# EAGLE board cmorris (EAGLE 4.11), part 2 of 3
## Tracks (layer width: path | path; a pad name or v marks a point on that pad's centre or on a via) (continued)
DQ6  (via drill 0.61)
  Top 0.203: v56.53,59.14 56.94,58.74 56.94,45.4 56.53,45 56.53,44.29 56.94,43.88 56.94,30.7 v56.53,30.29 | v78.86,25.64 v78.86,30.29 | v82.24,26.63 82.19,26.58 82.19,25.64 IC9.6
  Bottom 0.203: v56.53,59.14 39.75,59.14 39.39,59.5 IC17.13 | v78.86,30.29 v56.53,30.29 | v78.86,25.64 79.6,25.64 IC9.6 | v82.24,26.63 100.71,26.63 101.06,26.99 IC6.5
DQ7  (via drill 0.61)
  Top 0.203: v89.89,21.53 90.29,21.93 90.29,31.33 v89.89,31.74 90.29,32.04 90.29,39.74 v89.48,40.55 | v27.71,62.5 28.11,62.09 28.11,55.11 27.3,54.29 v27.3,48.43 | v34.41,44.21 v34.41,48.43 | v41.27,41.92 v41.27,43.9 | v76.22,40.68 v76.22,41.49
  Bottom 0.203: v89.89,31.74 90.47,31.74 90.78,32.04 101.04,32.04 101.06,32.07 IC6.3 | v89.89,21.53 89.66,21.3 82.16,21.3 81.81,20.94 IC9.8 | v27.71,62.5 37.18,62.5 IC17.12 | v34.41,48.43 v27.3,48.43 | v34.41,44.21 34.72,43.9 v41.27,43.9 | v41.27,41.92 41.45,41.75 51.66,41.75 51.73,41.82 52.24,41.82 52.7,41.36 55.49,41.36 55.6,41.47 56.08,41.47 56.38,41.77 75.94,41.77 v76.22,41.49 | v76.22,40.68 76.35,40.55 v89.48,40.55
DQ8  (via drill 0.61)
  Top 0.203: v113.74,33.44 113.71,33.41 113.71,31.56 113.74,31.53 v113.74,24.42 | v99.69,27.45 v99.69,24.07 | v98.47,27.45 98.06,27.04 v98.06,15.15 | v35.63,67.58 35.63,34.38 35.22,33.97 35.22,33.26 35.63,32.86 v35.63,12.84 | v72.89,23.53 v72.89,15.05
  Bottom 0.203: v113.74,33.44 115.08,33.44 115.39,33.74 130.42,33.74 130.78,33.39 IC2.18 | v113.74,24.42 110.94,24.42 110.59,24.07 v99.69,24.07 99.21,23.84 78.84,23.84 78.51,23.51 77.72,23.51 77.69,23.53 v72.89,23.53 | v98.47,27.45 v99.69,27.45 | v98.06,15.15 98.01,15.2 IC9.11 | v35.63,67.58 37.18,67.58 IC17.10 | v35.63,12.84 58.87,12.84 59.18,12.54 60.45,12.54 60.47,12.56 61.13,12.56 61.16,12.54 62.99,12.54 63.88,13.42 65.48,13.42 67.1,15.05 v72.89,15.05
DQ9  (via drill 0.61)
  Top 0.203: v98.88,25.82 98.47,25.41 98.47,19.88 v98.88,19.47 | v37.66,28.79 37.66,36.67 36.85,37.48 36.85,66.46 39.19,66.46 40.1,67.37 40.1,69.71 39.77,70.04 IC17.9 | v47.44,24.65 47.85,24.24 47.85,15.07 v47.44,14.67 | v54.5,17.46 v54.5,14.67
  Bottom 0.203: v98.88,25.82 100.48,25.82 101.29,26.63 125.06,26.63 125.09,26.66 130.45,26.66 130.78,26.99 IC2.16 | v98.88,19.47 98.85,19.5 89.56,19.5 89.43,19.62 IC9.13 87.6,19.62 86.33,18.35 82.32,18.35 81.91,18.76 79.88,18.76 78.73,17.61 59.1,17.61 58.95,17.46 v54.5,17.46 | v37.66,28.79 39.62,28.79 40.76,27.65 40.76,25.49 41.78,25.49 42.62,24.65 v47.44,24.65 | v54.5,14.67 v47.44,14.67
DQ10  (via drill 0.61)
  Top 0.203: v50.87,73.11 50.87,71.84 51.28,71.44 51.28,58.74 v50.87,58.33 | v63.34,58.26 63.34,48.58 63.75,48.17 v63.75,27.27 | v78.05,24.35 v78.05,27.27 | v96.79,25.08 v96.79,21.55
  Bottom 0.203: v50.87,73.11 39.77,73.11 IC17.8 | v50.87,58.33 51.18,58.64 55.88,58.64 56.26,58.26 v63.34,58.26 | v78.05,27.27 v63.75,27.27 | v78.05,24.35 87.24,24.35 87.6,24.7 IC9.15 89.81,25.08 v96.79,25.08 | v96.79,21.55 130.42,21.55 130.78,21.91 IC2.14
DQ11  (via drill 0.61)
  Top 0.203: v77.87,32.86 v77.87,31.94 | v53,36.31 v53,33.16 | v36.85,36.31 36.44,36.72 36.44,66.64 36.85,67.04 36.85,74.79 37.18,75.12 IC17.7 | v130.07,31.48 130.07,18.1 130.4,17.77 IC2.12
  Bottom 0.203: v77.87,31.94 81.61,31.94 82.39,31.15 87.55,31.15 87.6,31.1 IC9.17 89.63,30.9 90.22,30.9 90.93,31.61 113.66,31.61 113.81,31.46 114.47,31.46 114.73,31.71 122.98,31.71 123.01,31.69 126.06,31.69 126.18,31.56 129.99,31.56 v130.07,31.48 | v77.87,32.86 65.6,32.86 65.27,33.19 61.54,33.19 61.21,32.86 53.31,32.86 v53,33.16 | v36.85,36.31 v53,36.31
DRL  (via drill 0.61)
  Top 0.203: v148.79,57.6 149.37,58.18 149.37,63.36 149.7,63.69 IC5.2
  Bottom 0.203: v148.79,57.6 136.04,57.6 135.68,57.24 IC7.5
DRL\
  Top 0.203: IC7.6 133.45,53.79 133.12,53.45 133.12,50.2 133.45,49.87 133.45,41.26 133.42,41.24 133.42,25.82 132.99,25.39 IC2.15
EA1  (via drill 0.61)
  Top 0.203: v145.79,16.17 145.79,17.69 IC16.3 | v136.34,26.12 v136.34,16.47 | v127.73,24.42 v127.73,25.84 | v115.03,24.37 115.03,18.4 114.19,17.56 114.19,16.85 v113.79,16.45 | v93.82,16.78 93.54,16.5 v93.54,14.36 | v91.36,2.99 91.36,4.1 90.7,4.76 90.7,13.96 v90.29,14.36 90.7,14.67 v90.7,40.7 | SV1.5 v104.14,3.11 | v63.98,85.28 63.57,84.87 63.57,83.55 63.01,83 63.01,81.98 v62.91,81.88 | v45.99,81.55 46.4,81.14 46.4,74.92 45.99,74.51 45.99,71.41 v45.59,71.01 | v34.01,71.03 34.01,66.87 34.41,66.46 34.41,55.13 33.6,54.32 v33.6,50.56 | v34.82,50.56 35.22,50.15 35.22,39.59 v34.82,39.18 | v37.66,39.18 37.66,37.25 38.07,36.84 38.07,30.11 v38.58,29.6 | v49.14,29.48 49.14,28.46 IC19.2 | v81.71,41.47 81.71,54.7 81.3,55.11 81.3,77.41 80.92,77.79 v80.92,89.93 | v69.57,89.85 69.57,86.55 69.23,86.22 IC10.11
  Bottom 0.203: v145.79,16.17 145.46,16.5 138.25,16.5 138.22,16.47 v136.34,16.47 | v136.34,26.12 128.01,26.12 v127.73,25.84 | v127.73,24.42 127.25,24.42 126.44,23.61 125.78,23.61 125.37,24.02 122.4,24.02 122.37,24.04 121.71,24.04 121.66,23.99 115.41,23.99 v115.03,24.37 | v113.79,16.45 94.15,16.45 v93.82,16.78 | v90.29,14.36 v93.54,14.36 | v91.36,2.99 99.72,2.99 99.84,3.11 v104.14,3.11 | v63.98,85.28 66.98,85.28 67,85.31 IC10.11 | v62.91,81.88 62.88,81.9 56.38,81.9 55.98,81.5 55.32,81.5 54.91,81.9 46.35,81.9 v45.99,81.55 | v45.59,71.01 39.82,71.01 39.49,71.34 34.31,71.34 v34.01,71.03 | v34.82,50.56 v33.6,50.56 | v37.66,39.18 v34.82,39.18 | v38.58,29.6 38.7,29.48 v49.14,29.48 | v90.7,40.7 89.94,41.47 v81.71,41.47 | v80.92,89.93 80.51,90.34 76.53,90.34 76.04,89.85 v69.57,89.85
EA2  (via drill 0.61)
  Top 0.203: v60.9,3.42 v60.9,1.94 | v50.64,10.2 v50.64,3.42 | v45.03,10.2 45.44,10.61 45.44,24.73 44.95,25.21 44.95,26.2 IC19.4 | v106.68,1.94 SV1.7 | v144.5,15.66 144.5,17.67 IC16.2 | v134.56,16.45 134.16,16.04 134.16,15.81 133.32,14.97 133.32,3.19 131.26,1.13 124.48,1.13 v124.48,1.94
  Bottom 0.203: 105.93,1.19 105.86,1.13 61.72,1.13 v60.9,1.94 | 105.93,1.19 v106.68,1.94 | v50.64,3.42 v60.9,3.42 | v45.03,10.2 v50.64,10.2 | v144.5,15.66 135.53,15.66 134.74,16.45 v134.56,16.45 | v124.48,1.94 123.67,1.13 105.99,1.13 105.93,1.19
EA3  (via drill 0.61)
  Top 0.203: v39.95,9.05 40.36,9.46 40.36,25.72 39.87,26.2 IC19.6 | v37.26,1.94 v37.26,9.05 | v59.68,1.94 60.09,2.35 60.09,3.82 60.52,4.25 61.49,4.25 61.49,4 62.12,3.37 v62.12,3.01 | v74.75,3.01 75.48,2.27 78.68,2.27 v78.68,3.01 | v86.97,2.15 v86.97,3.01 | v97.94,6.16 v97.94,2.15 | v153.41,9.72 153.41,17.69 IC16.6 | v145.18,11.11 v145.18,9.72 | v131.64,12.71 v131.64,11.09 | v126.92,12.71 126.51,13.12 126.51,18.61 v126.92,19.01 | v113.74,19.75 113.38,19.39 v113.38,17.67 | v115.41,3.92 v115.41,17.03
  Bottom 0.203: v37.26,9.05 v39.95,9.05 | v37.26,1.94 38.07,1.13 58.87,1.13 v59.68,1.94 | v74.75,3.01 v62.12,3.01 | v86.97,3.01 v78.68,3.01 | v97.94,2.15 v86.97,2.15 | v97.94,6.16 108.56,6.16 108.91,5.8 SV1.9 109.52,4.28 109.88,3.92 v115.41,3.92 | v145.18,9.72 v153.41,9.72 | v145.18,11.11 142.44,11.11 142.29,10.96 131.77,10.96 v131.64,11.09 | v131.64,12.71 131.54,12.61 127.02,12.61 v126.92,12.71 | v126.92,19.01 121.48,19.01 121.31,19.19 120.72,19.19 120.52,19.39 114.09,19.39 v113.74,19.75 | v113.38,17.67 113.76,17.29 115.16,17.29 v115.41,17.03
EA\  (via drill 0.61)
  Top 0.203: v95.78,3.85 v95.78,12 | v83.46,2.17 v83.46,3.85 | v68.73,2.17 68.73,7.99 70.05,9.31 70.05,14.74 70.45,15.15 70.45,20 70.86,20.41 70.86,33.24 70.45,33.64 70.45,34.35 71.67,35.57 71.67,49.26 71.32,49.62 71.32,51.5 70.51,52.31 70.51,56.25 70.1,56.66 70.1,58.59 69.44,59.25 69.44,62.22 68.32,63.34 65.78,63.34 65.78,64.99 64.97,65.8 64.97,75.96 65.09,76.09 65.09,82.49 v65.5,82.89 | v101.59,12 SV1.4
  Bottom 0.203: v95.78,12 v101.59,12 | v83.46,3.85 v95.78,3.85 | v68.73,2.17 v83.46,2.17 | v65.5,82.89 66.87,82.89 IC10.10
EMA1  (via drill 0.61)
  Top 0.203: v8.63,25.49 8.63,23.51 IC14.3 | v52.19,73.95 52.19,74.89 52.42,75.12 IC17.34 | v30.96,73.9 30.55,73.5 30.55,25.59 v30.96,25.18
  Bottom 0.203: 30.96,25.49 33.57,25.49 33.9,25.82 IC19.8 | 30.96,25.49 v8.63,25.49 | v52.19,73.95 47.19,73.95 47.14,73.9 v30.96,73.9 | 30.96,25.49 v30.96,25.18
EMA2  (via drill 0.61)
  Top 0.203: v6.09,20.46 6.09,21.63 IC14.2 | v44.93,78.07 44.93,76.06 44.52,75.65 44.52,43.35 44.11,42.94 44.11,32.37 v44.52,31.97 | v28.01,31.97 28.01,20.89 28.44,20.46 IC19.11
  Bottom 0.203: v6.09,20.46 28.44,20.46 IC19.11 | v44.93,78.07 52.42,78.07 IC17.35 | v28.01,31.97 v44.52,31.97
EMA3  (via drill 0.61)
  Top 0.203: v4.36,28.16 4.36,32.58 3.96,32.98 3.96,47.89 3.55,48.3 IC4.1 | v15.41,28.16 15.01,27.75 15.01,23.53 IC14.6 | v48.43,80.2 48.03,79.79 48.03,74.21 47.62,73.8 47.62,63.67 48.43,62.85 v48.43,58.33 | v45.59,58.33 45.99,57.93 45.99,53.76 46.4,53.35 46.4,45.5 v45.99,45.1 | v42.49,45.1 42.49,43.52 42.9,43.12 42.9,23.2 v42.49,22.8 | v34.41,22.8 34.41,20.84 IC19.13
  Bottom 0.203: IC14.6 15.87,21.25 16.2,20.92 28.44,20.92 28.7,21.17 33.57,21.17 33.9,20.84 IC19.13 | v15.41,28.16 v4.36,28.16 | v48.43,80.2 52.42,80.2 IC17.36 | v45.59,58.33 v48.43,58.33 | v42.49,45.1 v45.99,45.1 | v34.41,22.8 v42.49,22.8
EMA4  (via drill 0.61)
  Top 0.203: v38.98,24.22 38.98,20.84 IC19.15 | v11.7,47.59 11.7,28.94 11.98,28.66 v11.98,24.32 | v40.43,71.84 v40.43,82.36 | v29.33,71.84 29.74,71.44 29.74,47.99 v29.33,47.59
  Bottom 0.203: 18.74,24.22 18.41,23.89 IC14.7 | v38.98,24.22 18.74,24.22 | v11.98,24.32 18.71,24.32 18.74,24.22 | IC4.2 5.71,47.92 6.04,47.59 v11.7,47.59 v29.33,47.59 | v40.43,82.36 52.8,82.36 IC17.37 | v29.33,71.84 v40.43,71.84
EMA5  (via drill 0.61)
  Top 0.203: v8.38,14.49 8.38,11.06 IC15.3 | v44.06,14.49 44.06,18.2 IC19.17 43.68,20.46 43.3,20.84 v43.3,43.88 | v6.17,24.47 6.57,24.88 6.57,29.04 6.62,29.1 6.62,36.51 6.98,36.87 6.98,47.92 7.36,48.3 IC4.3 | v4.19,14.49 v4.19,24.47 | v47.62,84.9 47.62,74.38 47.21,73.98 47.21,62.9 v47.62,62.5 | v45.59,62.5 45.99,62.09 45.99,59.25 46.4,58.84 46.4,53.94 46.81,53.53 46.81,44.29 v46.4,43.88
  Bottom 0.203: v44.06,14.49 v8.38,14.49 v4.19,14.49 | v4.19,24.47 v6.17,24.47 | v47.62,84.9 52.8,84.9 IC17.38 | v45.59,62.5 v47.62,62.5 | v43.3,43.88 v46.4,43.88
EWL  (via drill 0.61)
  Top 0.203: v90.6,98.54 90.6,96.69 89.68,95.77 89.68,92.42 89.02,92.42 88.03,91.43 88.03,89.6 88.44,89.19 88.44,88.84 IC20.2 | v97.71,99.45 v97.71,98.41 | v111.04,99.45 111.04,95.64 110.31,94.91 110.31,86.02 111.12,85.2 111.12,81.17 111.53,80.76 111.53,78.8 111.86,78.47 IC18.9 | v137.26,67.35 136.85,67.76 136.85,75.86 v137.26,76.26 | v133.5,76.26 133.5,84.92 v133.9,85.33 | v115.62,78.47 v115.62,85.36
  Bottom 0.203: v90.6,98.54 93.62,98.54 94.03,98.13 94.48,98.13 94.94,97.68 95.7,97.68 95.73,97.7 97,97.7 v97.71,98.41 | v97.71,99.45 97.73,99.48 111.02,99.48 v111.04,99.45 | v137.26,67.35 137.64,67.73 142.69,67.73 142.72,67.76 143.4,67.76 144.06,67.09 150.01,67.09 IC5.1 | v133.5,76.26 v137.26,76.26 | v133.9,85.33 133.78,85.2 115.77,85.2 v115.62,85.36 | v115.62,78.47 114.45,78.47 IC18.9
EWL\  (via drill 0.61)
  Top 0.203: v131.36,75.83 131.44,75.91 131.44,85.31 131.82,85.69 131.82,87.67 IC28.11
  Bottom 0.203: v131.36,75.83 114.45,75.83 IC18.8
EWLSET  (via drill 0.61)
  Top 0.203: v114.78,92.82 114.78,83.88 114.45,83.55 IC18.11 | v92.53,92.82 92.53,96.2 91.82,96.91 v91.82,97.04 | v89.78,97.04 88.69,98.13 87.78,98.13 87.78,98.08 86.81,97.12 v86.74,97.12 | v80.21,97.12 79.8,96.71 79.8,96.58 79.45,96.23 v79.45,93.87 | v76.96,93.87 76.55,93.46 76.55,93.03 75.94,92.42 72.94,92.42 v72.94,92.82 | v62.17,87.74 v62.17,92.82 | v28.85,86.98 28.85,84.19 IC27.6
  Bottom 0.203: v114.78,92.82 114.75,92.8 92.55,92.8 v92.53,92.82 | v89.78,97.04 v91.82,97.04 | v80.21,97.12 v86.74,97.12 | v76.96,93.87 v79.45,93.87 | v72.94,92.82 72.66,92.55 62.45,92.55 v62.17,92.82 | v62.17,87.74 61.79,87.36 59.13,87.36 58.77,87.01 35.99,87.01 35.96,86.98 v28.85,86.98
GND  (via drill 0.61)
  Top 1.016: v148,50.99 v148,49.7 | v134.74,49.7 IC7.7 | 160.75,31.81 161.11,31.46 161.11,20.89 v160.29,20.08 | 160.75,31.81 159.89,32.68 IC25.7 | v156.76,16.6 v156.76,12.71 v156.76,8.85 | v158.87,16.6 158.87,17.31 IC16.8 | v160.29,49.85 161.11,49.04 161.11,32.17 160.75,31.81 | v151,49.85 IC5.7 | v75.33,45.15 75.33,48.83 IC12.8 76.63,48.83 v76.63,48.04 | IC8.10 61.11,45.91 v61.11,45.12 61.01,44.62 v61.01,40.55 | C2.2 92.32,44.31 92.32,46.19 92.5,46.37 v92.5,47.36 92.5,49.06 92.35,49.21 IC11.8 90.14,48.83 v90.14,48.07 | IC24.8 v105.79,47.36 106.14,47 106.14,44.97 v106.17,44.95 | IC22.8 118.72,48.71 118.69,48.68 v118.69,44.49 v118.69,41.64 | v63.75,12.13 v63.75,14.26 | v79.98,11.92 79.98,14.54 IC9.10 | v100.68,13.42 100.68,14.67 IC6.10 103.27,14.67 103.3,14.64 v103.3,13.53 | 99.06,10.78 v99.06,13.42 | SV1.2 99.06,10.78 | v116.63,13.12 v116.63,15.38 | v98.57,10.78 99.06,10.78 | v84.17,11.67 v84.17,14.59 | v122.07,41.26 122.04,41.24 v122.04,38.34 | v112.11,38.34 112.11,31.41 112.52,31 112.52,25.72 112.11,25.31 v112.11,23.58 | v118.28,23.15 118.28,19.52 118.26,19.5 v118.26,15.38 | v144.09,12.79 144.09,12.21 143.96,12.08 v143.96,10.27 | v129.84,11.09 v129.84,9.87 | v124.89,11.09 124.89,14.29 IC2.10 | v129.56,99.05 130.02,99.51 130.02,99.53 130.35,99.86 132.23,99.86 v132.23,97.5 | v120.77,99.05 C1.2 v120.77,93.64 | v139.75,83.05 139.75,82.23 IC28.7 | v145.21,77.28 v145.21,72.91 | v144.37,77.28 v144.37,83.05 v144.37,88.61 144.57,89.12 v144.57,99.05 | v133.98,99.05 SV4.7 | 90.93,73.93 90.93,75.48 IC20.7 | C5.2 90.93,73.93 | v74.93,75.55 IC3.7 73.63,77.92 v73.63,76.9 | v60.32,76.39 IC10.7 | v99.89,73.93 v99.89,75.55
  Top 1.016: v91.41,73.93 90.93,73.93 | v57.75,76.39 v57.75,65.42 | v119.2,69.41 v119.2,70.83 119.68,71.06 119.68,72.84 120.39,73.55 120.39,83.43 119.43,84.39 v119.43,93.64 | v109.19,69.41 109.19,70.85 108.78,71.26 v108.78,72.89 | v107.97,72.89 108.02,72.94 108.02,74.21 106.83,75.4 IC18.7 | v22.12,62.7 v22.12,49.24 v22.12,43.78 v22.12,35.27 v22.12,23.41 | v25.07,65.95 24.96,65.85 v24.96,62.93 | v28.72,3.01 v28.72,7.15 | v28.82,23.41 28.82,25.82 IC19.10 | v23.52,21.73 v23.52,10.12 | v10.03,5.45 C9.2 | IC15.8 21.08,9.18 v21.08,5.45 v21.08,3.01 | v99.18,94.83 99.18,95.72 GND.MP | v88.26,95.29 C10.2 | v30.48,76.03 30.48,81.95 IC27.7 31.69,83.88 31.69,85.03 31.57,85.15 v31.57,85.51 | v24.02,76.03 v24.02,80.73 | v3.93,80.73 C6.2 | v35.63,90.84 v35.63,94.93 | v34.01,86.17 v34.01,90.84 | v78.99,98.62 78.99,99.12 78.25,99.86 76.55,99.86 v76.55,97.68 | v54.3,96.05 v54.3,97.68 | v26.89,65.95 26.89,75.63 26.82,75.7 C11.2 | v58.29,97.68 v58.29,78.63 | v55.85,37.88 v55.85,40.55 | v52.06,37.88 52.06,39.31 v51.07,40.3 | v31.77,43.37 v31.77,40.7
  Bottom 1.016: v148,49.7 v134.74,49.7 | v148,50.99 149.7,50.99 IC5.7 | v160.29,20.08 160.17,19.95 159.38,19.95 IC16.8 | v158.87,16.6 v156.76,16.6 | v156.76,8.85 C4.2 | v160.29,49.85 v151,49.85 | v61.11,45.12 74.59,45.12 74.62,45.15 v75.33,45.15 | v105.79,47.36 102.61,47.36 102.59,47.33 101.57,47.33 101.54,47.36 v92.5,47.36 | v118.69,44.49 116.38,44.49 116.35,44.51 115.34,44.51 115.31,44.49 113.81,44.49 113.38,44.92 106.85,44.92 106.83,44.95 v106.17,44.95 | v76.63,48.04 90.11,48.04 v90.14,48.07 | v63.75,14.26 61.16,14.26 61.11,14.21 IC1.10 | v63.75,12.13 63.8,12.18 65.22,12.18 65.48,11.92 v79.98,11.92 | v99.06,13.42 v100.68,13.42 | v116.63,15.38 v118.26,15.38 122.93,15.38 IC2.10 | v116.63,13.12 106.45,13.12 106.04,13.53 v103.3,13.53 | v98.57,10.78 93.59,10.78 C3.2 92.58,10.78 88.41,10.78 88.39,10.81 87.24,10.81 86.38,11.67 v84.17,11.67 | v84.17,14.59 81.86,14.59 IC9.10 | v118.69,41.64 121.69,41.64 v122.07,41.26 | v112.11,38.34 v122.04,38.34 | v112.11,23.58 112.14,23.58 112.57,23.15 v118.28,23.15 | v156.76,12.71 151.38,12.71 151.28,12.81 145.72,12.81 145.69,12.79 v144.09,12.79 | v143.96,10.27 143.15,10.27 142.74,9.87 v129.84,9.87 | v124.89,11.09 v129.84,11.09 | SV4.5 SV4.7 v132.23,97.5 | v120.77,99.05 121.18,99.45 129.15,99.45 v129.56,99.05 | v144.37,83.05 v139.75,83.05 | Q1.3 v144.37,88.61 | v145.21,72.91 149.96,72.91 IC21.7 | v144.37,77.28 v145.21,77.28 | v133.98,99.05 134.39,99.45 144.16,99.45 v144.57,99.05 | v74.93,75.55 88.36,75.55 IC20.7 | v73.63,76.9 73.12,76.9 72.72,76.49 69.84,76.49 69.79,76.54 66.16,76.54 66.06,76.65 61.84,76.65 61.59,76.39 v60.32,76.39 v57.75,76.39 | v99.89,75.55 104.24,75.55 IC18.7
  Bottom 1.016: v91.41,73.93 v99.89,73.93 | v57.75,65.42 57.27,65.42 56.84,64.99 55.01,64.99 IC17.30 | v109.19,69.41 v119.2,69.41 | v107.97,72.89 v108.78,72.89 | v119.2,70.83 C7.2 | v119.43,93.64 v120.77,93.64 | IC26.7 v22.12,62.7 22.6,62.93 v24.96,62.93 | IC4.8 v22.12,49.24 | v25.07,65.95 v26.89,65.95 37.51,65.95 37.56,65.9 IC17.11 | v28.72,7.15 33.88,7.15 34.31,7.58 SV2.2 | v28.72,3.01 R6.2 v21.08,3.01 | v28.82,23.41 v22.12,23.41 21.33,23.41 IC14.8 21.33,21.73 v23.52,21.73 | v23.52,10.12 IC15.8 | v22.12,35.27 IC13.8 | v21.08,5.45 v10.03,5.45 | v88.26,95.29 93.52,95.29 93.98,94.83 v99.18,94.83 | v30.48,76.03 C11.2 v24.02,76.03 | v24.02,80.73 v3.93,80.73 | v35.63,94.93 50.08,94.93 C8.2 51.2,96.05 v54.3,96.05 | v34.01,90.84 v35.63,90.84 | v34.01,86.17 32.23,86.17 v31.57,85.51 | v78.99,98.62 79.27,98.34 87.37,98.34 87.93,97.78 C10.2 | v54.3,97.68 v58.29,97.68 v76.55,97.68 | v58.29,78.63 59.05,78.63 IC10.7 | v55.85,40.55 v61.01,40.55 | v52.06,37.88 v55.85,37.88 | v51.07,40.3 49.35,40.3 48.94,40.7 v31.77,40.7 | v31.77,43.37 31.26,43.37 30.86,43.78 v22.12,43.78
INT_RQ\  (via drill 0.61)
  Top 0.203: v117.45,9.05 117.45,8.04 SV1.16 | v119.07,9.05 119.07,19.14 119.1,19.16 119.1,23.86 118.79,24.17 v118.79,25.31 | v121.23,25.31 121.23,41.59 122.09,42.46 124.07,42.46 v124.07,48.37 | v131.9,49.7 132.2,49.39 v132.2,45.83 | v138.02,45.83 138.48,46.29 138.48,52.59 138.07,53 138.07,53.71 138.48,54.12 v138.48,58.53 | v146.73,61.61 146.73,65.72 146.93,65.93 146.93,68.31 147.65,69.03 v147.65,74.13 | v155.21,74.13 155.62,74.54 155.62,81.7 155.21,82.11 155.21,85.13 v154.81,85.53
  Bottom 0.203: v119.07,9.05 v117.45,9.05 | v118.79,25.31 118.82,25.34 121.2,25.34 v121.23,25.31 | v124.07,48.37 124.86,49.16 125.78,49.16 126.61,50 131.59,50 v131.9,49.7 | v138.02,45.83 v132.2,45.83 | v138.48,58.53 139.77,58.53 139.82,58.48 140.48,58.48 140.53,58.53 140.94,58.53 141.35,58.13 143.38,58.13 144.55,59.3 145.03,59.3 145.92,60.19 145.92,61.61 v146.73,61.61 | v155.21,74.13 v147.65,74.13 | v154.81,85.53 157.58,85.53 IC21.13
IOP4\  (via drill 0.61)
  Top 0.203: v62.76,84.9 62.35,84.49 62.35,83.83 61.95,83.43 61.95,82.23 61.92,82.21 61.92,81.29 61.95,81.27 v61.95,74.74 | v104.72,74.28 104.72,73.83 105.13,73.42 v105.13,70.32 | v107.97,65.67 v107.97,70.32
  Bottom 0.203: v62.76,84.9 62.4,84.9 61.97,85.33 61.28,85.33 IC10.4 | v61.95,74.74 103.09,74.74 103.55,74.28 v104.72,74.28 | v107.97,70.32 v105.13,70.32 | v107.97,65.67 108.81,64.83 112.44,64.83 IC24.15
IOS\  (via drill 0.61)
  Top 0.203: v154.81,78.47 v154.81,80.1 | v127.27,78.5 127.27,79.69 IC28.2 | v121.61,78.5 121.2,78.09 121.2,73.19 120.49,72.48 120.49,68.31 122.02,66.79 122.02,62.07 122.04,62.04 122.04,54.06 120.92,52.95 120.01,52.95 119.6,52.54 118.18,52.54 118.18,49.34 117.88,49.04 v117.88,39.59 | v115.44,39.59 115.84,39.18 115.84,21.17 115.44,20.77 115.44,18.23 114.6,17.39 114.6,16.68 115.01,16.27 115.01,7.94 SV1.14 | v149.14,80.91 149.14,84.16 149.09,84.21 149.09,86.78 149.12,86.81 149.12,88.61 v149.22,88.71 | v147.59,88.71 148,89.12 v148,99.28 | v145.79,99.28 144.8,100.27 135.1,100.27 135.1,97.09 134.08,96.08 131.49,96.08 131.49,96.03 131.01,95.54 130.25,95.54 129.51,96.28 v129.46,96.28 | v116.51,98.23 v116.51,96.61 | v118.61,78.55 v118.61,98.23
  Bottom 0.203: v154.81,80.1 152.19,80.1 IC21.4 149.96,80.91 v149.14,80.91 | v154.81,78.47 157.58,78.47 IC21.10 | v127.27,78.5 v121.61,78.5 121.13,78.55 v118.61,78.55 | v115.44,39.59 v117.88,39.59 | v147.59,88.71 v149.22,88.71 | v145.79,99.28 v148,99.28 | v129.46,96.28 129.08,95.9 122.37,95.9 122.32,95.95 118.38,95.95 117.72,96.61 v116.51,96.61 | v118.61,98.23 v116.51,98.23
IOT601  (via drill 0.61)
  Top 0.203: v23.77,97.8 23.77,91.81 IC27.11 | v49.8,99.43 v49.8,97.8 | v64.87,99.43 64.87,91.38 65.27,90.97 65.27,89.09 65.76,88.61 65.76,84.75 65.81,84.7 v65.81,84.11 | v79.7,83.38 80.11,82.97 80.11,77.43 80.49,77.05 80.49,72.66 v80.08,72.25 | v94.84,72.71 94.84,76.65 95.98,77.79 95.98,78.04 IC20.9
  Bottom 0.203: v49.8,97.8 v23.77,97.8 | v64.87,99.43 v49.8,99.43 | v65.81,84.11 66.49,84.8 72.33,84.8 72.74,84.39 73.22,84.39 73.35,84.27 76.3,84.27 76.83,83.73 78.48,83.73 78.84,83.38 v79.7,83.38 | v80.08,72.25 89.17,72.25 89.78,72.86 94.69,72.86 v94.84,72.71
IOT602\  (via drill 0.61)
  Top 0.203: v148,45.81 148,35.01 148.46,34.56 IC25.3 | v140.53,47.46 v140.53,45.81 | v130.35,48.73 v130.35,53.33 130.35,64.94 130.32,64.96 130.32,65.11 129.53,65.9 129.53,66.61 129.94,67.02 129.94,70.12 129.53,70.52 129.53,71.23 130.15,71.84 130.15,76.37 130.63,76.85 130.63,79.97 130.55,80.05 IC28.3 129.28,81.93 129.28,86.65 v129.05,86.88 | v124.48,56.5 v124.48,53.05 | v108.53,51.8 v108.53,58.13
  Bottom 0.203: v140.53,45.81 v148,45.81 | v140.53,47.46 140.31,47.23 131.85,47.23 v130.35,48.73 | v130.35,53.33 130.09,53.07 128.65,53.07 128.62,53.05 v124.48,53.05 | v124.48,56.5 124.48,57.11 124.07,57.52 124.07,58.46 121.36,58.46 121.03,58.13 v108.53,58.13 | v108.53,51.8 107.08,51.8 IC24.7 | v129.05,86.88 120.87,86.88 120.85,86.86 104.41,86.86 103.81,87.47 102.28,87.47 101.87,87.87 98.7,87.87 98.29,87.47 92.5,87.47 92.4,87.57 91.74,87.57 91.64,87.47 88.64,87.47 88.31,87.8 83.56,87.8 IC3.12
IOT604\  (via drill 0.61)
  Top 0.203: v143.89,36.74 143.89,34.91 IC25.1 | v144.7,36.74 145.11,37.15 145.11,59.73 v144.7,60.14 | v124.89,50 125.29,50.41 125.29,57.47 v124.89,57.87 | v133.42,57.87 133.45,57.9 133.45,58.87 IC7.4 | v137.26,91.38 137.26,89.9 IC28.9 138.17,87.67 138.53,87.31 v138.53,60.24
  Bottom 0.203: v144.7,36.74 v143.89,36.74 | 138.53,60.14 136.04,60.14 135.68,59.78 IC7.4 | 138.53,60.14 v144.7,60.14 | v124.89,50 114.68,50 114.32,49.64 IC24.9 | v133.42,57.87 v124.89,57.87 | v137.26,91.38 129.92,91.38 129.28,92.01 83.97,92.01 83.48,91.53 IC3.13 | v138.53,60.24 138.53,60.14
IOT612\  (via drill 0.61)
  Top 0.203: v125.12,83.02 125.12,82.28 IC28.1 124.2,80.05 124.2,79.97 123.74,79.52 123.74,72.38 v124.15,71.97 | v126.74,83.02 126.74,87.67 IC28.13 | v134.36,83.05 134.36,81.93 IC28.5 | v110.41,54.27 110.81,54.67 110.81,60.82 110.41,61.23 v110.41,71.97
  Bottom 0.203: v125.12,83.02 v126.74,83.02 127.22,83.12 134.28,83.12 v134.36,83.05 | v110.41,54.27 107.08,54.27 IC24.6 | v124.15,71.97 v110.41,71.97
IOT614\  (via drill 0.61)
  Top 0.203: v50.03,25.11 50.03,20.46 IC19.19 | v51.68,25.11 51.68,25.82 IC19.1 | IC15.11 14.73,18.68 14.6,18.81 14.6,28.87 14.98,29.25 IC14.11 | v49.55,23.66 49.55,24.88 v50.03,25.11 | v24.73,19.39 v24.73,22.19 | v115.03,46.29 115.03,50.91 114.7,51.25 IC24.10 | v126.51,46.29 126.11,45.89 v126.11,35.12 | v149.8,35.5 v149.8,36.59 | IC16.11 153.41,27.19 153.13,27.47 153.13,35.75 153.16,35.78 153.16,36.18 v153.56,36.59 153.16,36.89 153.16,46.9 153.49,47.23 153.49,52.59 v153.59,52.69 | v50.03,33.19 50.44,32.78 50.44,25.41 v50.03,25.11 | v45.33,30.32 v45.33,33.19 | v44.11,30.32 43.71,30.72 43.71,43.12 44.11,43.52 v44.11,76.42 | v50.06,76.42 50.06,82.23 50.46,82.64 50.46,85.38 50.87,85.79 v50.87,88.1 | v51.68,88.1 53.21,89.62 55.75,89.62 v55.75,90.44 | v64.46,86.53 v64.46,90.44 | v76.96,84.8 77.36,85.2 77.36,91.58 v76.96,91.99 | v78.99,91.99 78.58,92.39 78.58,95.95 79.4,96.76 79.4,97.47 79.88,97.95 85.01,97.95 85.01,95.82 85.39,95.44 85.39,94.88 v85.8,94.48 | v87.22,94.48 87.22,89.83 88.03,89.01 88.03,88.08 89.17,86.93 91.26,86.93 91.26,86.37 91.28,86.35 v91.28,79.44 | v102.69,73.04 v102.69,76.77
  Bottom 0.203: v51.68,25.11 v50.03,25.11 | v49.55,23.66 39.59,23.66 39.31,23.38 35,23.38 34.74,23.63 30.22,23.63 28.77,22.19 v24.73,22.19 | v24.73,19.39 15.95,19.39 15.62,19.06 IC15.11 | v126.51,46.29 v115.03,46.29 | v126.11,35.12 130.4,35.12 IC2.19 132.99,35.47 149.78,35.47 v149.8,35.5 | v149.8,36.59 v153.56,36.59 | v45.33,33.19 v50.03,33.19 | v44.11,30.32 v45.33,30.32 | v50.06,76.42 v44.11,76.42 | v51.68,88.1 v50.87,88.1 | v55.75,90.44 56.13,90.06 64.08,90.06 v64.46,90.44 | v64.46,86.53 64.84,86.91 69.01,86.91 69.97,85.94 69.97,85.23 72.49,85.23 72.89,84.82 73.91,84.82 73.93,84.8 v76.96,84.8 | v78.99,91.99 v76.96,91.99 | v87.22,94.48 v85.8,94.48 | v91.28,79.44 93.26,79.44 93.65,79.06 94.51,79.06 96.26,77.31 101.19,77.31 101.72,76.77 v102.69,76.77 | v102.69,73.04 106.95,73.04 108.5,74.59 116.73,74.59 117.14,74.18 117.8,74.18 118.21,74.59 130.86,74.59 130.88,74.56 131.85,74.56 131.87,74.59 137,74.59 137.38,74.21 141.45,74.21 141.5,74.16 146.5,74.16 147.31,74.97 147.97,74.97 148.38,74.56 152.19,74.56 153.28,75.65 153.28,75.73 153.77,76.21 154.43,76.21 154.66,75.98 157.17,75.98 157.83,76.65 159.91,76.65 161.51,75.04 161.51,66.79 161.11,66.38 161.11,59.63 161.51,59.22 161.51,52.69 v153.59,52.69
IOT621  (via drill 0.61)
  Top 0.203: v63.47,80.68 63.47,75.15 63.75,74.87 63.75,63.34 v63.34,62.93 | v86.89,63.21 87.3,62.8 87.3,57.29 v86.89,56.88 | v89.02,56.88 89.81,56.1 92.68,56.1 v92.68,58.66 | v103.75,58.94 104.57,58.13 107.72,58.13 107.72,58.48 108.2,58.97 109.19,58.97 109.19,58.64 109.6,58.23 v109.6,57.21 | v123.26,57.62 122.86,57.21 122.86,53.66 123.26,53.25 123.26,50.46 124.56,49.16 125.29,49.16 125.29,40.15 v124.89,39.74 | v131.34,44.97 v131.34,39.74 | v138.88,53.35 v138.88,44.97 | v147.75,62.52 v147.75,53.33 | v154.1,62.52 153.69,62.93 153.69,74.97 v154.1,75.38
  Bottom 0.203: v63.47,80.68 61.61,80.68 IC10.6 | v63.34,62.93 74.52,62.93 74.82,63.23 79.09,63.23 79.14,63.18 82.42,63.18 82.44,63.21 v86.89,63.21 | v89.02,56.88 v86.89,56.88 | v92.68,58.66 92.98,58.97 97.33,58.97 97.66,58.64 103.45,58.64 v103.75,58.94 | v109.6,57.21 111.98,57.21 112.39,57.62 v123.26,57.62 | v131.34,39.74 v124.89,39.74 | v138.88,44.97 v131.34,44.97 | v138.88,53.35 139.16,53.07 141.35,53.07 141.37,53.05 147.47,53.05 v147.75,53.33 | v154.1,62.52 v147.75,62.52 | v154.1,75.38 157.58,75.38 IC21.9
IOT621\  (via drill 0.61)
  Top 0.203: v57.07,83.15 57.47,82.74 v57.47,77.61 | v70.71,82.56 v70.71,79.67 | v84.37,82.26 84.78,81.85 84.78,71.69 v84.37,71.28 | v89.38,65.75 v89.38,71.28 | v117.88,63.51 117.47,63.11 117.47,57.01 v117.88,56.6
  Bottom 0.203: v57.07,83.15 59.02,83.15 IC10.5 | v57.47,77.61 57.78,77.31 61.34,77.31 63.44,79.41 70.45,79.41 v70.71,79.67 | v70.71,82.56 73.6,82.56 73.91,82.26 76.35,82.26 76.63,82.54 81.25,82.54 81.53,82.26 v84.37,82.26 | v89.38,71.28 v84.37,71.28 | v89.38,65.75 103.22,65.75 103.73,65.24 107.23,65.24 107.64,64.83 108.22,64.83 109.85,63.21 117.57,63.21 v117.88,63.51 | v117.88,56.6 IC22.5
IOT622\  (via drill 0.61)
  Top 0.203: v100.66,83.3 100.58,83.22 100.58,81.17 100.71,81.04 100.71,61.12 | v100.71,56.88 100.71,61.12 | v66.72,73.93 66.31,74.33 66.31,79.49 66.72,79.9 66.72,80.51 IC10.9 | v88.51,66.61 v88.51,73.93 | v93.19,61.51 v93.19,66.56 | v100.63,61.12 100.71,61.12
  Bottom 0.203: v100.66,83.3 98.57,83.3 IC20.11 | v100.71,56.88 104.49,56.88 IC24.5 | v66.72,73.93 67.1,74.31 88.13,74.31 v88.51,73.93 | v88.51,66.61 88.54,66.59 89.71,66.59 90.04,66.26 92.88,66.26 v93.19,66.56 | v93.19,61.51 97.33,61.51 97.71,61.12 v100.63,61.12
IOT624\  (via drill 0.61)
  Top 0.203: v62.53,34.15 v62.53,35.75 | IC8.1 58.9,69.15 58.57,68.82 58.57,46.17 60.19,44.54 IC1.1 | v78.25,50.18 77.85,49.77 77.85,37.81 78.33,37.33 v78.33,36.21 | v69.84,36.21 69.84,35.5 69.23,34.89 69.23,34.28 69.11,34.15 IC1.19
  Bottom 0.203: v62.53,35.75 61.11,35.75 IC1.1 | v62.53,34.15 66.52,34.15 IC1.19 | v78.25,50.18 80.82,50.18 81.15,50.51 89.86,50.51 90.19,50.84 100.02,50.84 101.75,52.57 102.13,52.57 102.13,53.02 104.19,55.08 112.14,55.08 112.49,54.72 IC24.11 | v69.84,36.21 v78.33,36.21
LAD
  Top 0.203: IC3.9 IC3.10 IC3.11
LAD\  (via drill 0.61)
  Top 0.203: 81.71,70.32 81.71,55.28 82.14,54.85 IC12.11 | 81.71,70.32 81.71,77.56 IC3.8 | v31.77,44.62 31.36,45.02 31.36,68.44 v31.77,68.85 | v48.84,68.85 48.84,78.85 49.65,79.67 49.65,82.41 50.06,82.82 v50.06,86.14 | v84.2,86.96 84.2,83.6 85.19,82.61 85.19,70.93 84.78,70.52 v84.78,70.07 | 81.71,70.32 v82.11,70.32 | v107.72,50.79 v107.72,55.89 | v102.94,55 v102.94,50.81
  Bottom 0.203: v31.77,44.62 21.79,44.62 21.76,44.59 16.25,44.59 15.87,44.21 IC13.11 | v48.84,68.85 v31.77,68.85 | v50.06,86.14 52.27,86.14 52.7,86.58 58.92,86.58 59.28,86.93 61.82,86.93 61.84,86.91 62.5,86.91 62.94,87.34 72.23,87.34 72.56,87.01 73.22,87.01 73.55,87.34 78.56,87.34 78.66,87.24 79.32,87.24 79.42,87.34 83.81,87.34 v84.2,86.96 | v84.78,70.07 84.53,70.32 v82.11,70.32 | v107.72,55.89 108.02,55.59 128.62,55.59 128.65,55.61 129.87,55.61 129.89,55.59 141.04,55.59 141.42,55.97 IC7.10 | v107.72,50.79 107.44,50.51 103.25,50.51 v102.94,50.81 | v102.94,55 99.82,55 IC11.11
N$1  (via drill 0.61)
  Top 0.203: C11.1 IC27.5 26.31,84.19 v26.31,86.14 | v30.48,86.14 30.48,89.57 IC27.8
  Bottom 0.203: v26.31,86.14 v30.48,86.14
N$2  (via drill 0.61)
  Top 0.203: IC21.12 IC21.11 157.58,80.45 157.25,80.12 v157.25,77.23 | v153.69,54.45 153.69,57.42 153.28,57.82 v153.28,77.23
  Bottom 0.203: v153.69,54.45 151.94,54.45 IC5.6 | v157.25,77.23 v153.28,77.23
N$3  (via drill 0.61)
  Top 0.203: v148.2,85.38 148.41,85.59 148.41,86.68 148.71,86.98 148.71,88 148.41,88.3 148.41,92.06 148.69,92.34 R3.2 | v147.01,85.33 146.83,85.15 146.83,79.77 146.43,79.36 146.43,69.79 v146.83,69.38 | v135.63,69.38 136.04,69.79 136.04,87.26 135.63,87.67 IC28.10
  Bottom 0.203: v148.2,85.38 148.15,85.33 v147.01,85.33 | v135.63,69.38 v146.83,69.38
N$4  (via drill 0.61)
  Top 0.203: v72.89,83.55 v72.89,87.85
  Bottom 0.203: v72.89,87.85 68.88,87.85 IC10.12 | v72.89,83.55 73.63,83.55 IC3.5
N$5  (via drill 0.61)
  Top 0.203: v135.12,86.07 135.12,86.2 133.98,87.34 133.98,90.23 132.38,90.23 131.41,91.2 131.41,92.55 R4.2
  Bottom 0.203: Q1.1 v135.12,86.07
N$6  (via drill 0.61)
  Top 0.203: v137.79,95.8 137.94,95.95 137.94,97.9 138.65,98.62 142.06,98.62 142.06,98.56 142.87,97.75 v143.07,97.75
  Bottom 0.203: v137.79,95.8 136.9,95.8 136.83,95.72 SV4.6 | R5.2 v143.07,97.75
N$10
  Top 0.203: IC13.13 10.54,37.3 9.57,36.34 9.57,29.12 10.18,28.51 10.54,28.51 IC14.4
N$11  (via drill 0.61)
  Top 0.203: v86,64.12 v86,59.83 | v79.47,64.02 79.24,64.25 v79.24,67.88 | v73.63,68.29 73.22,68.69 73.22,75.27 v73.63,75.68 | v78.46,76.8 78.58,76.92 78.58,79.39 78.18,79.79 78.18,96.71 v78.58,97.12 | v36.44,96.86 36.44,67.22 36.04,66.81 v36.04,33.62
  Bottom 0.203: v86,59.83 84.73,59.83 IC12.13 | v86,64.12 84.86,64.12 84.45,63.72 79.78,63.72 v79.47,64.02 | v79.24,67.88 78.86,68.26 76.81,68.26 76.78,68.29 v73.63,68.29 | v73.63,75.68 74.75,76.8 v78.46,76.8 | v78.58,97.12 78.33,96.86 v36.44,96.86 | v36.04,33.62 11.12,33.62 10.79,33.95 IC13.4
N$12
  Bottom 0.203: IC11.13 93.09,59.65 92.09,60.64 82.39,60.64 81.76,60.01 81.76,59.65 IC12.4
N$13  (via drill 0.61)
  Top 0.203: v154.5,53.53 154.5,54.8 154.1,55.21 v154.1,59.88 | v148.56,76.44 v148.56,59.6 | v140.31,77.69 v140.31,76.44 | v117.39,78.09 117.8,78.5 117.8,95.36 v117.39,95.77 | v109.34,94.65 v109.34,95.77 | v100.4,94.88 100.15,94.63 100.15,94.37 100.12,94.35 v100.12,86.53 | v94.61,84.52 v94.61,86.53 | v78.99,84.39 78.89,84.49 78.89,87.97 v78.99,88.08
  Bottom 0.203: v154.5,53.53 157.32,53.53 IC5.9 | v154.1,59.88 148.84,59.88 v148.56,59.6 | v140.31,76.44 v148.56,76.44 | v140.31,77.69 117.8,77.69 v117.39,78.09 | v109.34,95.77 v117.39,95.77 | v109.34,94.65 100.63,94.65 v100.4,94.88 | v100.12,86.53 98.73,86.53 98.32,86.93 96.24,86.93 95.83,86.53 v94.61,86.53 | v94.61,84.52 91.89,84.52 91.77,84.39 v78.99,84.39 | v78.99,88.08 76.22,88.08 IC3.3
N$14  (via drill 0.61)
  Top 0.203: v11.55,11.47 11.55,23.58 10.94,24.19 10.94,29.02 IC14.13
  Bottom 0.203: v11.55,11.47 10.56,11.47 10.54,11.44 IC15.4
N$15
  Top 0.203: IC5.10 IC5.11
N$17  (via drill 0.61)
  Top 0.203: v102.61,82.33 v102.61,88.3 | v122.93,83.73 v122.93,82.26 | v148.33,77.71 v148.33,83.73
  Bottom 0.203: v102.61,88.3 98.57,88.3 IC20.13 | v102.61,82.33 104.44,82.33 104.52,82.26 v122.93,82.26 | v122.93,83.73 123.06,83.86 148.2,83.86 v148.33,83.73 | v148.33,77.71 150.16,77.71 IC21.5
N$19  (via drill 0.61)
  Top 0.203: v92.5,80.28 92.86,79.92 92.86,77.38 92.58,77.1 92.58,76.39 92.98,75.98 92.98,71.69 v92.58,71.28 | v94.69,70.88 94.81,70.75 v94.81,58.13 | v123.67,61.53 v123.67,59.8 | v125.37,61.53 125.37,71.92 v125.78,72.33 | v155.49,65.47 v155.49,72.07 | v156.99,65.47 156.99,62.55 v157.02,62.52
  Bottom 0.203: v92.5,80.28 90.65,80.28 IC20.5 | v92.58,71.28 92.96,70.9 94.66,70.9 v94.69,70.88 | v94.81,58.13 106.8,58.13 107.97,59.3 107.97,59.83 108.07,59.83 108.45,60.21 109.11,60.21 109.49,59.83 112.06,59.83 112.47,60.24 114.93,60.24 115.23,60.54 115.59,60.54 115.62,60.57 121.2,60.57 121.97,59.8 v123.67,59.8 | v125.37,61.53 v123.67,61.53 | v125.78,72.33 125.83,72.38 126.56,72.38 126.59,72.4 132.35,72.4 132.69,72.07 v155.49,72.07 | v156.99,65.47 v155.49,65.47 | v157.02,62.52 156.21,61.71 152.29,61.71 IC5.3
N$21  (via drill 0.61)
  Top 0.203: v141.14,92.22 v141.14,87.08 | v135.63,92.22 134.79,91.38 131.82,91.38 131.82,93.36 129.97,95.21 129.97,95.24 129.74,95.47 128.24,95.47 v128.24,96.74 | v114.37,97.42 113.97,97.83 113.97,98.18 111.88,100.27 108.33,100.27 107.13,99.07 99.03,99.07 99.03,98.56 97.71,97.24 v97.71,96.86 | v96.06,96.86 95.65,96.46 95.65,82.49 v95.63,82.46 | v79.29,79.84 v79.29,81.73
  Bottom 0.203: v141.14,87.08 146.58,87.08 147.34,86.32 150.19,86.32 IC21.2 | v135.63,92.22 v141.14,92.22 | v128.24,96.74 126.67,96.74 126.31,96.38 125.4,96.38 125.37,96.41 121.26,96.41 121.23,96.38 120.31,96.38 120.29,96.41 118.51,96.41 117.5,97.42 v114.37,97.42 | v96.06,96.86 v97.71,96.86 | v95.63,82.46 90.75,82.46 90.14,81.85 85.14,81.85 84.7,81.42 83.89,81.42 83.59,81.73 v79.29,81.73 | v79.29,79.84 78.63,79.19 71.39,79.19 71.04,78.83 69.01,78.83 IC10.8
N$22  (via drill 0.61)
  Top 0.203: v23.21,70.32 23.21,81.6 IC27.4
  Bottom 0.203: v23.21,70.32 IC26.8
N$23  (via drill 0.61)
  Top 0.203: R7.1 v153.16,87.34
  Bottom 0.203: v153.16,87.34 Q1.2
NED  (via drill 0.61)
  Top 0.203: IC20.6 88.36,78.6 88.03,78.93 88.03,85.33 88.36,85.66 IC20.3 | v156.89,58.03 156.89,48.48 157.3,48.07 157.3,45.25 156.89,44.84 156.89,42.53 IC25.9 | v92.07,86.73 92.07,84.98 92.55,84.49 93.39,84.49 93.39,84.67 93.8,85.08 93.8,86.88 95.25,88.33 95.25,98.46 v95.3,98.51 | v119.55,95.11 v119.55,99.45 | v121.99,95.11 121.59,94.7 121.59,90.72 121.2,90.34 v121.2,86.04 | v130.3,86.04 131.03,85.31 131.03,76.67 130.55,76.19 130.55,72.38 v131.57,71.36 | v152.06,69.43 v152.06,71.26 | v160.29,69.43 160.7,69.03 160.7,58.28 v160.29,57.87
  Bottom 0.203: IC5.4 151.94,58.26 152.17,58.03 v156.89,58.03 157.37,57.87 v160.29,57.87 | v92.07,86.73 91.92,86.58 90.6,86.58 IC20.3 | v95.3,98.51 95.25,98.56 94.18,98.56 93.67,99.07 93.67,100.27 118.74,100.27 v119.55,99.45 | v121.99,95.11 v119.55,95.11 | v130.3,86.04 v121.2,86.04 | v131.57,71.36 131.67,71.26 v152.06,71.26 | v160.29,69.43 v152.06,69.43
NOERR  (via drill 0.61)
  Top 0.203: v92.09,81.62 v92.09,83.45 | v94.74,81.62 94.74,80.89 95.02,80.61 95.02,79.74 v95.42,79.34 | v109.67,80 109.67,78.55 110.03,78.19 110.03,76.95 110.43,76.54 v110.43,73.37 | v131.77,73.37 133.42,75.02 135.02,75.02 v135.02,73.75 | v143.99,72.94 143.99,71.49 v145.21,70.27 | v157.58,70.45 157.58,72.84 IC21.8
  Bottom 0.203: v92.09,83.45 90.95,83.45 IC20.4 | v94.74,81.62 v92.09,81.62 | v95.42,79.34 102.74,79.34 103.17,79.77 104.49,79.77 104.54,79.72 107.54,79.72 107.95,80.12 109.55,80.12 v109.67,80 | v110.43,73.37 110.79,73.72 131.41,73.72 v131.77,73.37 | v135.02,73.75 140.61,73.75 140.63,73.77 141.3,73.77 142.13,72.94 v143.99,72.94 | v145.21,70.27 145.56,70.62 151.35,70.62 151.74,70.24 152.4,70.24 152.78,70.62 155.93,70.62 156.1,70.45 v157.58,70.45
OE\  (via drill 0.61)
  Top 0.203: v82.93,37.78 v82.93,36.16 | v72.82,80.1 v72.82,67.37 | v47.62,57.42 47.62,54.47 48.03,54.06 48.03,40.25 47.62,39.84 47.62,39.13 48.03,38.72 v48.03,38.27 48.2,37.76 v48.2,30.32 | v50.06,67.96 v50.06,57.42 | v55.72,68.8 55.72,70.42 v55.75,70.45 | v62.94,67.17 v62.94,69.74 | v38.48,38.27 IC17.20 | v65.38,40.5 64.97,40.09 64.97,33.49 65.78,32.68 v65.78,28.51 | v54.63,26.61 55.04,27.01 55.04,29.91 v54.63,30.32
  Bottom 0.203: v82.93,36.16 87.57,36.16 IC9.19 | v82.93,37.78 82.19,37.78 IC9.1 79.88,38.62 67.48,38.62 66.9,39.21 66.9,40.5 v65.38,40.5 | v72.82,67.37 68.91,67.37 IC8.19 66.52,67.17 v62.94,67.17 | v72.82,80.1 73.98,80.1 IC3.6 | v48.03,38.27 v38.48,38.27 | v50.06,57.42 v47.62,57.42 | v50.06,67.96 50.08,67.98 51.89,67.98 52.7,68.8 v55.72,68.8 | v55.75,70.45 61.87,70.45 62.58,69.74 v62.94,69.74 | v65.78,28.51 61.95,28.51 60.7,27.27 59.18,27.27 58.52,26.61 v54.63,26.61 | v48.2,30.32 v54.63,30.32
PWRCLR  (via drill 0.61)
  Top 0.203: v108.35,10.38 108.35,8.75 108.28,8.67 108.28,8.17 108.1,7.99 108.1,7.48 107.13,6.51 107.13,6.16 103.04,6.16 103.02,6.13 103.02,6.06 102.33,5.37 SV1.3 | 117.45,13.53 117.45,19.85 117.47,19.88 117.47,23.15 117.06,23.56 117.06,70.73 v117.47,71.13 | 117.45,13.53 v117.45,10.38 | v98.12,72.45 98.12,75.15 IC20.8 | v151.61,28.71 151.61,32.32 IC25.4 | v147.87,23.1 v147.87,28.71 | v138.3,21.98 138.7,21.58 138.7,15.25 v138.3,14.85 | v127.91,15.96 127.91,10.27 v127.5,9.87 | v123.54,13.12 v123.54,10.99 | 117.45,13.53 v117.85,13.53
  Bottom 0.203: v117.45,10.38 v108.35,10.38 | v117.47,71.13 108.33,71.13 108.07,71.39 102.33,71.39 101.27,72.45 v98.12,72.45 | v147.87,28.71 v151.61,28.71 | v147.87,23.1 142.39,23.1 141.96,23.53 141.45,23.53 140.94,24.04 137.97,24.04 137.49,23.56 137.49,21.98 v138.3,21.98 | v138.3,14.85 137.92,15.23 135.38,15.23 135,15.61 133.07,15.61 132.71,15.96 v127.91,15.96 | v127.5,9.87 127.12,10.25 124.28,10.25 v123.54,10.99 | v123.54,13.12 123.16,13.5 117.88,13.5 v117.85,13.53
SCL\  (via drill 0.61)
  Top 0.203: v103.5,90.62 v103.5,81.5 | v107.56,90.62 v107.56,88.99 | v145.92,63.95 145.92,42.18 IC25.13 | v140.41,64.86 v140.41,66.13 | v123.46,87.72 123.74,87.44 123.74,80.1 123.34,79.69 123.34,69.81 v123.74,69.41 | v133.8,69.41 133.8,67.4 IC7.1
  Bottom 0.203: v103.5,81.5 98.22,81.5 IC20.10 | v103.5,90.62 104.24,90.62 IC18.1 106.83,90.62 v107.56,90.62 | v107.56,88.99 112.21,88.99 IC18.13 114.09,87.72 v123.46,87.72 | v145.92,63.95 143.66,63.95 IC7.13 141.42,64.86 v140.41,64.86 | v140.41,66.13 135.68,66.13 IC7.1 | v133.8,69.41 v123.74,69.41
TRC  (via drill 0.61)
  Top 0.203: v152.88,57.06 152.88,75.04 152.55,75.38 IC21.6 | v122.02,89.98 v122.02,81.45 | v127.73,90.64 127.91,90.82 v127.91,93.74 | v132.76,92.22 v132.76,93.74 | v134.41,92.22 135.25,93.05 138.12,93.05 138.12,90.62 v138.17,90.56 | v142.95,90.56 143.35,90.16 143.35,88.63 143.56,88.43 143.56,75.65 v143.81,75.4
  Bottom 0.203: v152.88,57.06 152.8,56.99 151.94,56.99 IC5.5 | v122.02,81.45 121.74,81.73 106.83,81.73 106.47,81.37 IC18.5 | v122.02,89.98 122.4,90.36 127.45,90.36 v127.73,90.64 | v127.91,93.74 128.24,94.07 132.43,94.07 v132.76,93.74 | v134.41,92.22 v132.76,92.22 | v142.95,90.56 v138.17,90.56 | v143.81,75.4 149.96,75.4 IC21.6
V+  (via drill 0.61)
  Top 0.203: IC18.4 104.24,83.55 103.91,83.88 103.91,87.74 104.24,88.08 IC18.2 | IC22.15 IC22.14 | IC18.10 111.86,81.01 111.53,81.34 111.53,85.2 111.86,85.53 IC18.12 | v122.93,80.45 v122.93,64.53 | v108.86,85.53 v108.86,83.73 | v147.19,39.21 147.19,34.56 IC25.2 | v148.81,39.21 148.81,39.94 IC25.12 148.81,42.53 v148.81,55.03 | v133.32,18.48 133.32,15.56 132.99,15.23 IC2.11 | v134.72,18.48 135.12,18.88 135.12,25.41 134.72,25.82 134.72,31.59 v134.31,31.99 | v158.39,31.89 158.39,27.29 158.49,27.19 IC16.9 | v132.18,64.5 132.58,64.91 132.58,69.84 v132.18,70.24 | v143.99,70.24 143.99,60.59 143.89,60.49 143.89,59.65 143.99,59.55 v143.99,55.03 | IC27.10 26.67,91.45 26.67,93.84 R1.1 | IC27.2 IC27.13 | v77.47,3.11 SV2.31 | v24.73,17.74 24.33,17.34 24.33,9.26 v24.35,9.23 | v29.54,9.23 29.54,3.42 v29.94,3.01 | v27.3,89.19 27.3,79.41 27.71,79.01 27.71,71.13 28.52,70.32 28.52,54.34 v28.11,53.94 | v25.37,35.67 v25.37,53.94 | v23.34,35.67 22.93,35.27 22.93,22.31 22.7,22.09 22.7,18.25 v22.3,17.84 | v107.13,14.36 106.75,13.98 106.75,11.44 105.86,10.55 105.86,8.88 v105.68,8.7 | v88.92,8.5 88.92,7.23 89.15,7 v89.15,5.04
  Bottom 0.203: v122.93,64.53 126.36,64.53 IC22.15 128.93,64.5 v132.18,64.5 | v122.93,80.45 114.45,80.45 IC18.10 | v108.86,83.73 106.65,83.73 IC18.4 | v108.86,85.53 111.86,85.53 IC18.12 | v147.19,39.21 v148.81,39.21 149.12,39.61 153.56,39.61 153.89,39.94 IC25.10 | v134.72,18.48 v133.32,18.48 | 145.94,31.99 v134.31,31.99 | 145.94,31.99 146.27,32.32 IC25.2 | v158.39,31.89 145.97,31.89 145.94,31.99 | v143.99,70.24 v132.18,70.24 | v148.81,55.03 v143.99,55.03 | IC27.2 IC27.1 | IC27.13 18.69,89.22 19.02,88.89 25.42,88.89 25.75,89.22 IC27.10 26.31,89.22 26.34,89.19 v27.3,89.19 | IC15.10 IC15.9 22.3,17.74 | v77.47,3.11 77.08,3.49 75.43,3.49 75,3.92 61.82,3.92 61.49,4.25 60.57,4.25 60.24,3.92 51.66,3.92 51.33,4.25 50.31,4.25 49.85,3.8 32.71,3.8 R2.1 v29.94,3.01 | v24.73,17.74 22.3,17.74 | v29.54,9.23 v24.35,9.23 | SV2.31 77.82,5.75 79.19,5.75 79.6,6.16 81.89,6.16 82.24,5.8 SV2.35 SV2.37 SV2.39 v89.15,5.04 | v25.37,53.94 v28.11,53.94 | v23.34,35.67 v25.37,35.67 | v22.3,17.84 22.3,17.74 | v107.13,14.36 108.15,14.36 108.56,13.96 110.64,13.96 111.04,14.36 118.18,14.36 118.61,13.93 123.19,13.93 123.21,13.96 123.87,13.96 123.9,13.93 125.09,13.93 125.45,14.29 130.78,14.29 IC2.11 | v105.68,8.7 89.48,8.7 89.28,8.5 v88.92,8.5
VCC  (via drill 0.61)
  Top 1.016: IC24.16 v113.41,68.19 | v96.24,68.44 96.24,69.99 96.01,70.22 C5.1 | v128.72,68.59 128.72,67.25 IC22.16 126.87,67.42 126.87,68.19 | v142.36,68.57 IC7.14 | v147.75,65.93 v147.75,67.93 | v158.62,67.93 IC5.14 | 126.87,68.19 C7.1 | v126.39,68.19 126.87,68.19 | v147.19,90.51 147.19,92.32 R5.1 145.79,93.16 v145.79,95.34 | v158.87,90.95 IC21.14 | 125.47,94.96 125.47,96.76 C1.1 | 125.47,94.96 125.47,91.2 | 125.47,91.2 125.47,89.55 IC28.14 | v124.99,91.2 125.47,91.2 | v125.95,94.96 125.47,94.96 | v139.06,93.43 SV4.4 | v133.98,93.43 SV4.8 | v16.51,94.2 16.51,91.45 IC27.14 | v67.94,96.05 IC10.14 | v53.72,93.71 IC17.40 | C8.1 v55.88,93.71 | v97.28,93.61 IC20.14 | C10.1 v93.34,93.74 | v88.87,94.07 v88.87,93.26 | 86,70.07 86,86.2 86.41,86.6 v86.41,93.26 | 86,70.07 v86,66.97 | v82.52,69.1 82.52,67.93 IC12.16 | v107.31,93.79 +5V.MP | v81.61,95.9 81.61,94.07 IC3.14 | v24.58,96.79 v24.58,94.2 | v34.01,93.71 v34.01,96.89 | v113.15,97.83 IC18.14 | v92.5,68.44 92.48,68.47 92.48,69.25 92.17,69.56 v92.17,70.07 | 86,70.07 v86.48,70.07 86.89,70.37 86.89,74.82 87.22,75.15 v87.22,88.66 | v3.63,64.94 3.63,69.2 IC26.14 | 2.36,57.87 v2.36,60.92 | 2.36,57.87 IC4.16 | v3.15,47.21 3.15,44.21 IC13.16 | v2.36,51.27 1.95,51.68 1.95,57.57 2.36,57.87 | v22.3,15.3 v22.3,4.23 | v3.37,15.71 3.37,16.73 3.3,16.8 IC15.16 2.03,18.68 1.54,19.16 1.54,28.51 2.28,29.25 IC14.16 2.33,31.18 2.33,33.21 v2.36,33.24 | v15.11,4.23 C9.1 | v141.35,41.24 v141.35,36.31 IC16.16 141.98,25.31 142.06,25.23 142.06,22.31 v142.03,22.29 | v155.14,11.49 v155.14,13.93 | v151.38,14.03 v151.38,11.49 | v139.92,22.29 v139.92,14.41 | v58.16,37.88 v58.16,20.08 | v66.9,37.83 66.9,37.07 IC1.20 v67.81,39.46
  Top 1.016: v97.2,37.55 97.15,37.61 97.15,39.23 | C2.1 97.15,39.23 | v108.56,39.23 108.56,38.34 IC6.20 | v97.63,39.23 97.15,39.23 | v128.65,38.77 128.65,40.98 128.14,41.49 v128.14,43.27 | v113.81,46.14 v113.81,43.27 | v109.19,43.27 v109.19,46.14 | v104.92,39.74 v104.92,43.27 | v91.51,37.55 v91.51,6.31 | v84.68,38.34 v84.68,39.48 | v37.33,12 v37.33,15.3 | v51.68,12 51.68,18.2 IC19.20 | v84.58,95.09 v84.58,88.66 | v52.14,94.53 52.14,93.79 52.01,93.66 52.01,90.77 v51.68,90.44 | v40.51,92.06 v40.51,90.79 | v32.79,92.06 32.79,85.66 32.91,85.53 v32.91,83.73 | v34.01,77.31 v34.01,83.73 | v34.82,72.66 v34.82,77.31 | v20.62,67.48 v20.62,73.52 | v7.79,65.24 v7.79,67.88
  Bottom 1.016: 99.61,67.96 99.84,68.19 v113.41,68.19 v126.39,68.19 | 99.61,67.96 99.59,67.93 IC11.16 | 99.61,67.96 99.13,68.44 v96.24,68.44 v92.5,68.44 | v142.36,68.57 136.55,68.57 136.14,68.16 133.32,68.16 132.89,68.59 v128.72,68.59 | v147.75,67.93 v158.62,67.93 | v147.75,65.93 143.5,65.93 143.3,66.13 IC7.14 | SV4.4 SV4.2 142.29,95.34 v145.79,95.34 | v158.87,90.95 150.74,90.95 150.31,90.51 v147.19,90.51 | v124.99,91.2 114.42,91.2 IC18.14 | v125.95,94.96 128.42,94.96 128.49,94.88 132.18,94.88 132.25,94.96 SV4.8 | v133.98,93.43 v139.06,93.43 | v16.51,94.2 R1.2 v24.58,94.2 | C6.1 15.23,89.62 IC27.14 | C8.1 56.28,96.05 v67.94,96.05 77.92,96.05 78.08,95.9 v81.61,95.9 | v55.88,93.71 v53.72,93.71 v34.01,93.71 | v88.87,93.26 v86.41,93.26 83.84,93.26 IC3.14 | v88.87,94.07 92.96,94.07 v93.34,93.74 93.47,93.61 v97.28,93.61 107.13,93.61 v107.31,93.79 | v86,66.97 84.7,66.97 IC12.16 | v82.52,69.1 78.73,69.1 78.71,69.08 77.19,69.08 76.53,69.74 69.08,69.74 IC8.20 | v24.58,96.79 24.68,96.89 v34.01,96.89 | v113.15,97.83 108.25,97.83 +5V.MP | v86.48,70.07 v92.17,70.07 | v2.36,60.92 1.54,60.92 1.54,63.87 2.48,64.81 3.5,64.81 v3.63,64.94 4.03,65.24 v7.79,65.24 | v3.15,47.21 2.33,47.21 1.54,47.99 1.54,50.48 2.33,51.27 v2.36,51.27 | v22.3,4.23 v15.11,4.23 | v3.37,15.71 8.88,15.71 9.29,15.3 v22.3,15.3 v37.33,15.3 | v2.36,33.24 2.33,33.24 1.54,34.02 1.54,36.51 1.57,36.54 1.57,36.61 1.54,36.64 1.54,40.45 2.66,41.57 IC13.16 | v141.35,41.24 IC25.14 | v151.38,11.49 v155.14,11.49 | v151.38,14.03 145.21,14.03 145.18,14.01 143.81,14.01 143.4,14.41 v139.92,14.41 | v142.03,22.29 v139.92,22.29 | v155.14,13.93 C4.1 | v58.16,20.08 54.1,20.08 53.54,19.52 IC19.20
  Bottom 1.016: v58.16,37.88 65.35,37.88 65.4,37.83 v66.9,37.83 | v97.2,37.55 v91.51,37.55 89.58,37.55 IC9.20 87.22,38.34 v84.68,38.34 | v97.63,39.23 104.92,39.23 | 104.92,39.23 v108.56,39.23 | v128.65,38.77 130.47,38.77 130.78,38.47 IC2.20 132.99,37.61 135.5,37.61 136.8,36.31 v141.35,36.31 | v113.81,43.27 v128.14,43.27 | v109.19,46.14 v113.81,46.14 | v104.92,43.27 v109.19,43.27 | v104.92,39.74 104.92,39.23 | v91.51,6.31 C3.1 | v67.81,39.46 79.47,39.46 79.5,39.48 v84.68,39.48 | v51.68,12 v37.33,12 | v84.58,88.66 v87.22,88.66 | v84.58,95.09 57.17,95.09 56.61,94.53 v52.14,94.53 | v51.68,90.44 47.52,90.44 47.16,90.79 v40.51,90.79 | v32.79,92.06 v40.51,92.06 | v34.01,83.73 v32.91,83.73 | v34.82,77.31 v34.01,77.31 | v34.82,72.66 30.25,72.66 29.79,73.11 29.15,73.11 28.75,73.52 v20.62,73.52 | v20.62,67.48 18.89,67.48 18.49,67.88 v7.79,67.88
WE\  (via drill 0.61)
  Top 0.203: v107.29,37.53 v107.29,35.57 | v28.11,87.97 28.11,89.4 IC27.9 | v24.84,74.82 v24.84,87.97 | v30.4,10.63 30.8,11.04 30.8,18.3 30.14,18.96 v30.14,74.82 | v100.68,41.62 100.68,38.09 IC6.1 | v95.93,42.36 95.98,42.41 95.98,45.02 97.05,46.09 97.05,52.21 96.77,52.49 v96.64,52.49 | v85.36,53.89 85.19,54.06 85.19,64.99 86.81,66.61 86.81,67.88 v87.22,68.29 | v57.75,64.17 58.16,63.77 58.16,54.47 v57.75,54.06 | v50.06,55.64 v50.06,54.39 | v42.54,55.64 42.49,55.69 42.49,58.28 v42.54,58.33 | v33.6,58.64 34.01,59.04 34.01,66.28 33.6,66.69 33.6,70.27 33.19,70.68 v33.19,74.74
  Bottom 0.203: v107.29,35.57 108.33,35.57 IC6.19 | IC6.1 103.27,37.53 v107.29,37.53 107.49,37.02 107.69,36.82 122.45,36.82 122.91,36.36 125.01,36.36 125.42,35.95 128.52,35.95 129.05,36.49 129.05,37.1 128.52,37.63 125.37,37.63 IC2.1 | v24.84,87.97 v28.11,87.97 | SV3.9 24.76,74.89 v24.84,74.82 v30.14,74.82 30.63,74.74 v33.19,74.74 | IC17.39 52.8,88.76 52.45,89.12 31.75,89.12 31.52,88.89 29.18,88.89 28.85,89.22 IC27.9 | v30.4,10.63 R2.2 | v100.68,41.62 96.67,41.62 v95.93,42.36 | v96.64,52.49 95.58,53.56 89.99,53.56 89.66,53.89 v85.36,53.89 | v87.22,68.29 82.88,68.29 82.85,68.26 82.39,68.26 80.89,66.76 80.89,66.56 80.82,66.56 80.41,66.15 78.38,66.15 78.35,66.18 77.69,66.18 77.26,65.75 74.06,65.75 73.68,66.13 71.7,66.13 71.17,65.6 71.17,63.36 64.08,63.36 63.67,63.77 61.64,63.77 61.23,63.36 58.57,63.36 v57.75,64.17 | v57.75,54.06 50.39,54.06 v50.06,54.39 | v50.06,55.64 50.03,55.66 42.56,55.66 v42.54,55.64 | v42.54,58.33 42.23,58.64 v33.6,58.64
WR\1  (via drill 0.61)
  Top 0.203: v3.81,58.89 3.81,61.76 IC26.1 | v5.13,58.89 5.13,58.1 IC4.15 | v4.44,64.02 SV3.1
  Bottom 0.203: v5.13,58.89 v3.81,58.89 | v4.44,64.02 4.42,64 3.45,64 IC26.1
WR\2  (via drill 0.61)
  Top 0.203: v6.34,58.89 6.34,61.76 IC26.2 5.43,64 v5.43,68.29 | v7.67,58.89 7.67,58.1 IC4.14 | v2.97,72.35 v2.97,77.43
  Bottom 0.203: v7.67,58.89 v6.34,58.89 | v2.97,72.35 3.37,71.95 3.58,71.95 4.69,70.83 4.69,68.29 v5.43,68.29 | v2.97,77.43 SV3.2
WR\3  (via drill 0.61)
  Top 0.203: v8.88,58.89 8.88,61.76 IC26.3 | v10.21,58.89 10.21,58.1 IC4.13 | v6.98,64.02 SV3.3
  Bottom 0.203: v10.21,58.89 v8.88,58.89 | v6.98,64.02 7,64 7.97,64 IC26.3
WR\4  (via drill 0.61)
  Top 0.203: v11.42,58.89 11.42,61.76 IC26.4 11.42,63.64 11.83,64.05 11.83,73.01 v12.24,73.42 | v12.75,58.89 12.75,58.1 IC4.12 | v5.86,73.42 5.86,76.72 6.24,77.1 SV3.4
  Bottom 0.203: v12.75,58.89 v11.42,58.89 | v12.24,73.42 v5.86,73.42
WR\5  (via drill 0.61)
  Top 0.203: v13.96,58.89 13.96,61.76 IC26.5 | v15.29,58.89 15.29,58.1 IC4.11 | v9.52,64.33 SV3.5
  Bottom 0.203: v15.29,58.89 v13.96,58.89 | v9.52,64.33 12.72,64.33 13.05,64 IC26.5
WR\6  (via drill 0.61)
  Top 0.203: v16.51,58.89 16.51,61.76 IC26.6 15.23,63.64 14.85,64.02 v14.85,72.35 | v17.9,58.89 17.9,58.18 IC4.10 | v10.61,72.35 10.64,72.38 10.64,76.72 10.26,77.1 SV3.6
  Bottom 0.203: v17.9,58.89 v16.51,58.89 | v14.85,72.35 v10.61,72.35
WR\7  (via drill 0.61)
  Top 0.203: SV3.7 11.42,74.46 11.42,71.26 IC26.11 11.42,69.38 11.42,65.55 v11.02,65.14 | v21.31,65.14 21.31,57.82 IC4.9
  Bottom 0.203: v11.02,65.14 v21.31,65.14
WR\8  (via drill 0.61)
  Top 0.203: v8.4,76.31 8.4,71.62 IC26.12 | v19.4,68.69 v19.4,50.61
  Bottom 0.203: v8.4,76.31 11.4,76.31 11.75,76.67 SV3.8 | v19.4,50.61 18.46,50.61 18.41,50.56 IC4.7 | v19.4,68.69 8.86,68.69 8.53,69.03 IC26.12
WRITELOCK_LED
  Bottom 0.203: SV4.1 141.91,96.74 142.06,96.58 148.76,96.58 149.14,96.97 R3.1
